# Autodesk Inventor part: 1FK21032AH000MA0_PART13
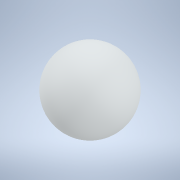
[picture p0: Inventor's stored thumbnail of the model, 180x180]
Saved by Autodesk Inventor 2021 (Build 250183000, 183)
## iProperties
Created: 2025-04
Part Number: 1FK21032AH000MA0_PART13
Material: Generic
Catalog Web Link: www.3dfindit.com
Description: -Servo synchronous motor
Document SubType Name: Modeling
Designer: psAdmin
Mass: 0.113097 g
Surface Area: 1.13097 cm^2
Volume: 0.113097 cm^3
Density: 1 g/cm^3
Appearance: PSOLRGB-212-217-219
Category: PARTsolutions
Title: 1FK21032AH000MA0_PART13
Author: Cadenas PARTsolutions
Comments: Servo synchronous motor
Sending System: PARTsolutions
Preprocessor: ST-DEVELOPER v19.3
PSOL_IDENT_0: {$CADENAS_DATA/23d-libs/siemens_ag/_cat_/45/10/1fk21032ah000ma0.prj},216 {VTYP=3D},{NB=1FK21032AH000
PSOL_IDENT_1: MA0_PART13},{LINA=1FK21032AH000MA0_PART13},{NN=1FK21032AH000MA0_PART13},{NOPRJ=TRUE},{DATE=19.08.202
PSOL_IDENT_2: 5 14:00:35},{GEOMDATE=30.07.2025 02:02:03},{VERSION=},{LINEID=10},{WBVAR=},{WBNUMERIC=}  {NB=1FK2103
PSOL_IDENT_3: 2AH000MA0_PART13},{LINA=1FK21032AH000MA0_PART13},{KT=DUMMY},{PREVIEW=../../../_pool_/14/8e/p_d211_xx
PSOL_IDENT_4: _00426j.png},{DESCSHORT=SIMOTICS S-1FK2 HD, SINAMICS S210 3AC 400V-480V, 0.59 Nm, 4500 rpm},{DESCLON
PSOL_IDENT_5: G=SIMOTICS S-1FK2 HD servo motor M0=0.64 Nm; PN = 0.28 kW at nN=4500 rpm (380-480 V); PN = 0.167 kW
PSOL_IDENT_6: at nN=2500 rpm (200-240 V); degree of protection IP64; cylindrical shaft D14 x 30 mm; absolute encod
PSOL_IDENT_7: er 22-bit + 12-bit multiturn (encoder AM22DQC); with OCC interface; plug size M17, rotatable; SIMOTI
PSOL_IDENT_8: CS S-1FK2 servomotorfor a wide range of uses in industrial environments. SIMOTICS S‑1FK2 servomotors
PSOL_IDENT_9: are compact synchronous motors with a high dynamic performance that set themselves apart as a resul
PSOL_IDENT_10: t of their high power density, degree of protection and overload capability. The motors are availabl
PSOL_IDENT_11: e in two variants: as High Dynamic variant (highest dynamic performance as a result of the low intri
PSOL_IDENT_12: nsic moment of inertia for applications demanding a high dynamic performance with low moved masses)
PSOL_IDENT_13: - and as Compact variant (precise and stable closed-loop control for medium up to large moved masses
PSOL_IDENT_14: as a result of a medium intrinsic moment of inertia). SIMOTICSS‑1FK2 servomotors fully exploit thei
PSOL_IDENT_15: r strengths in a system with the SINAMICSS210 frequency converter and simple connection using the on
PSOL_IDENT_16: e cable connection (OCC). Advantages include the short control and positioning times, fast and preci
PSOL_IDENT_17: se correction of disturbing quantities as well as stable control with a high dynamic performance. Th
PSOL_IDENT_18: e servo motors can be configured to address a wide range of requirements. For example with and witho
PSOL_IDENT_19: ut holding brake, IP64 or IP65 degree of protection, singleturn or multiturn absolute encoders - to
PSOL_IDENT_20: name just a few. Further, the servomotors are available in different shaft heights extending from 20
PSOL_IDENT_21: to 100. A shaft sealing ring is available to achieve an IP65 degree of protection and for subsequen
PSOL_IDENT_22: t mounting at the motor or as spare part. SIMOTICS - the optimum motor for each and every motion con
PSOL_IDENT_23: trol application.},{INTNO=195125335004},{SUPPLIERALTNO=1FK2103-2AH00-0MA0},{MANUID=1FK21032AH000MA0}
PSOL_IDENT_24: ,{MANUNAME=Siemens},{MANUTYPEDESC=SYNCHRONOUS MOTOR 1FK2 HD 0,64 NM},{AAU732=SIMOTICS},{AAO057=S-1FK
PSOL_IDENT_25: 2},{AAU734=SIMOTICS S-1FK2 HD servo motor M0=0.64 Nm; PN = 0.28 kW at nN=4500 rpm (380-480 V); PN =
PSOL_IDENT_26: 0.167 kW at nN=2500 rpm (200-240 V); degree of protection IP64; cylindrical shaft D14 x 30 mm; absol
PSOL_IDENT_27: ute encoder 22-bit + 12-bit multiturn (encoder AM22DQC); with OCC interface; plug size M17, rotatabl
PSOL_IDENT_28: e;},{AAW338=SYNCHRONOUS MOTOR 1FK2 HD 0,64 NM},{AAO742=SIMOTICS},{AAO663=4034106444624},{NOCUPEROU=1
PSOL_IDENT_29: },{PRICEQUANTITY=1},{QUANTITYMIN=1},{QUANTITYINT=1},{CTN=85015100},{COO=RO},{AAO676=1FK2103-2AH00-0M
PSOL_IDENT_30: A0},{AAO677=Siemens AG},{ORDERUNIT=C62},{CONTENTUNIT=C62}
NB: 1FK21032AH000MA0_PART13
NT: Servo synchronous motor
NBSYN: $MANUID._PART13
LINA: 1FK21032AH000MA0_PART13
CATALOG: SIEMENS
PREVIEW: ../../../_pool_/14/8e/p_d211_xx_00426j.png
DESCSHORT: SIMOTICS S-1FK2 HD, SINAMICS S210 3AC 400V-480V, 0.59 Nm, 4500 rpm
DESCLONG: SIMOTICS S-1FK2 HD servo motor M0=0.64 Nm; PN = 0.28 kW at nN=4500 rpm (380-480 V); PN = 0.167 kW at nN=2500 rpm (200-240 V); degree of protection IP64; cylindr
INTNO: 195125335004
SUPPLIERALTNO: 1FK2103-2AH00-0MA0
MANUID: 1FK21032AH000MA0
MANUNAME: Siemens
MANUTYPEDESC: SYNCHRONOUS MOTOR 1FK2 HD 0,64 NM
AAU732: SIMOTICS
AAO057: S-1FK2
AAU734: SIMOTICS S-1FK2 HD servo motor M0=0.64 Nm; PN = 0.28 kW at nN=4500 rpm (380-480 V); PN = 0.167 kW at nN=2500 rpm (200-240 V); degree of protection IP64; cylindr
AAW338: SYNCHRONOUS MOTOR 1FK2 HD 0,64 NM
AAO742: SIMOTICS
AAO663: 4034106444624.0
NOCUPEROU: 1
PRICEQUANTITY: 1
QUANTITYMIN: 1
QUANTITYINT: 1
CTN: 85015100
COO: RO
ARTICLENO: 1FK21032AH000MA0_PART13
BOMINFO: 1FK21032AH000MA0_PART13
CREATOR: CADENAS GmbH
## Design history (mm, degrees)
feature "2025_04_17_15_00_20_0760"
body "Solid1"
